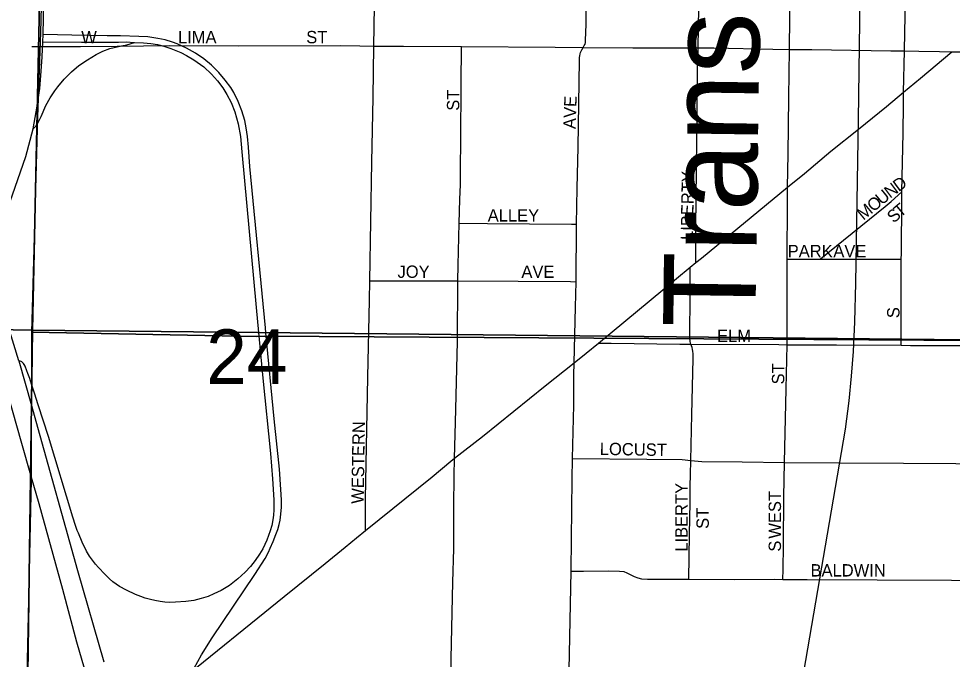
# Model space of a CAD drawing. Extents: x 0 to 68, y 0 to 52.9.
# Drawn here: x 43.122 to 43.878, y 37.686 to 38.205 of the extents above; entities that cross this region are included whole.
import ezdxf

# ---------------------------------------------------------------- set-up
doc = ezdxf.new("R2010")
doc.units = 0
for name, color, linetype in [('Default', 7, 'Continuous'), ('GM_X_County_Road', 7, 'Continuous'), ('GM_X_State_Route', 7, 'Continuous'), ('GM_X_Township', 7, 'Continuous')]:
    doc.layers.add(name, color=color, linetype=linetype)

msp = doc.modelspace()

# ---------------------------------------------------------------- linework, layer by layer
at = {"layer": 'Default'}
for points in [[(41.82896, 39.29088), (43.1609, 39.26536), (43.13273, 37.95279), (41.80876, 37.97561)], [(43.1609, 39.26536), (44.47349, 39.25009), (44.45233, 37.93902), (44.41032, 37.93957), (43.13273, 37.95279)], [(41.80876, 37.97561), (43.13273, 37.95279), (43.11555, 36.67874), (43.11455, 36.64024), (41.78766, 36.70713)], [(43.13273, 37.95279), (44.41032, 37.93957), (44.34414, 36.66665), (43.11555, 36.67874)]]:
    msp.add_lwpolyline(points, close=True, dxfattribs=at)
for points in [[(43.64162, 32.7683), (43.64334, 34.0176), (43.64455, 34.6783), (43.65599, 35.34849), (43.66788, 36.0083), (43.67702, 36.44587), (43.68602, 36.84543), (43.69035, 37.04683), (43.69592, 37.28989), (43.69757, 37.31546), (43.70235, 37.35703), (43.70606, 37.38349), (43.71865, 37.45038), (43.791, 37.87267), (43.79415, 37.89545), (43.79589, 37.91564), (43.79763, 37.93547), (43.7985, 37.95966), (43.79937, 37.99098), (43.80146, 38.12323), (43.80732, 38.54108), (43.80967, 38.71924)], [(43.40919, 38.18305), (43.41081, 38.27968)], [(43.57869, 38.18188), (43.57951, 38.18337), (43.58021, 38.18463), (43.58049, 38.18586), (43.58065, 38.18752), (43.58109, 38.20082), (43.58122, 38.25908), (43.58168, 38.27883)], [(43.67164, 38.18167), (43.67319, 38.26371), (43.67332, 38.27852)], [(43.74576, 38.18028), (43.7465, 38.25844), (43.74697, 38.27753)], [(43.83881, 38.17917), (43.8391, 38.19389), (43.84014, 38.24738), (43.8407, 38.26698), (43.84082, 38.27585)], [(43.26368, 37.67887), (43.26961, 37.68964), (43.27833, 37.70357), (43.31272, 37.75472), (43.32107, 37.76777), (43.32378, 37.77299), (43.32536, 37.77604), (43.32775, 37.78142), (43.32994, 37.78721), (43.33143, 37.7912), (43.33243, 37.79519), (43.33322, 37.79888), (43.33392, 37.80367), (43.33442, 37.80925), (43.33451, 37.81523), (43.33395, 37.8238), (43.33275, 37.84019), (43.32846, 37.88105), (43.32177, 37.95071), (43.32139, 37.95459), (43.3089, 38.08532), (43.30766, 38.10117), (43.30676, 38.10985), (43.30576, 38.11663), (43.30466, 38.12261), (43.30237, 38.13039), (43.29937, 38.13817), (43.29578, 38.14534), (43.29338, 38.14943), (43.28882, 38.15532), (43.28361, 38.16165), (43.2778, 38.16745), (43.27149, 38.1727), (43.26472, 38.17735), (43.25756, 38.18138), (43.25006, 38.1847), (43.24621, 38.18612), (43.24026, 38.18803), (43.23432, 38.18921), (43.22622, 38.19035), (43.219, 38.19082), (43.20413, 38.19128), (43.19338, 38.19141), (43.16465, 38.19183), (43.14133, 38.19231)], [(43.13232, 38.18265), (43.15203, 38.18259), (43.17173, 38.1827), (43.20128, 38.18295), (43.244, 38.18358), (43.29988, 38.18321), (43.38203, 38.18338), (43.39795, 38.18314), (43.40919, 38.18305)], [(43.13345, 38.11605), (43.13577, 38.11838), (43.13752, 38.12094), (43.13973, 38.12583), (43.14372, 38.13492), (43.14698, 38.14092), (43.15081, 38.14661), (43.15326, 38.15006), (43.15857, 38.1563), (43.16435, 38.16211), (43.17021, 38.16716), (43.1773, 38.17194), (43.18428, 38.17613), (43.18964, 38.17881), (43.19545, 38.18091), (43.20481, 38.18306), (43.20907, 38.18406), (43.21536, 38.1858), (43.22257, 38.18557), (43.22865, 38.1851), (43.23398, 38.18419), (43.23922, 38.18279), (43.2448, 38.18105), (43.25283, 38.17767), (43.25748, 38.17534), (43.26355, 38.17186), (43.27146, 38.16604), (43.27764, 38.16023), (43.28271, 38.15471), (43.2869, 38.14912), (43.29008, 38.14364), (43.29362, 38.13735), (43.29658, 38.12968), (43.29933, 38.11985), (43.30132, 38.10959), (43.30227, 38.09717), (43.31391, 37.97108), (43.31584, 37.95077), (43.31934, 37.91399), (43.32541, 37.85284), (43.32714, 37.83238), (43.32833, 37.81532), (43.32824, 37.80715), (43.32804, 37.80296), (43.32744, 37.79917), (43.32645, 37.79449), (43.32525, 37.7902), (43.32395, 37.78651), (43.32246, 37.78272), (43.31917, 37.77564), (43.31659, 37.77125), (43.313, 37.76617), (43.30921, 37.76138), (43.30512, 37.75669), (43.29904, 37.7512), (43.29237, 37.74602), (43.28549, 37.74182), (43.27971, 37.73903), (43.27502, 37.73703), (43.26944, 37.73524), (43.26336, 37.73384), (43.25698, 37.73293), (43.2485, 37.73233), (43.24372, 37.73224), (43.24003, 37.73243), (43.23624, 37.73292), (43.23195, 37.73372), (43.22836, 37.73462), (43.22397, 37.73571), (43.22039, 37.73691), (43.21629, 37.7385), (43.20902, 37.74199), (43.20313, 37.74518), (43.19795, 37.74886), (43.19515, 37.75126), (43.19146, 37.75495), (43.18618, 37.76043), (43.18375, 37.76329), (43.17889, 37.76978), (43.1764, 37.77378), (43.1729, 37.78096), (43.16991, 37.78824), (43.16906, 37.79051)], [(43.1412, 38.18642), (43.17243, 38.1862), (43.19013, 38.18621), (43.2024, 38.18622), (43.20852, 38.18632), (43.21536, 38.1858)], [(43.4059, 37.99287), (43.40762, 38.08886), (43.4085, 38.1414), (43.40919, 38.18305)], [(43.40919, 38.18305), (43.42365, 38.18293), (43.43332, 38.18291), (43.48019, 38.18263)], [(43.47836, 38.03937), (43.47892, 38.05871), (43.47922, 38.07081), (43.47942, 38.0889), (43.47974, 38.10146), (43.47997, 38.15761), (43.48014, 38.17717), (43.48019, 38.18263)], [(43.48019, 38.18263), (43.55598, 38.18218), (43.57869, 38.18188)], [(43.57327, 38.03856), (43.57388, 38.06772), (43.57458, 38.10113), (43.5756, 38.17138), (43.57564, 38.17375), (43.57586, 38.17516), (43.57611, 38.17662), (43.57651, 38.17791), (43.57747, 38.17989), (43.57869, 38.18188)], [(43.57869, 38.18188), (43.61876, 38.18153), (43.67164, 38.18167)], [(43.66992, 38.00751), (43.66987, 38.0153), (43.66976, 38.03616), (43.67003, 38.0589), (43.67086, 38.13228), (43.67125, 38.16453), (43.67164, 38.18167)], [(43.67164, 38.18167), (43.68437, 38.18143), (43.73226, 38.18054), (43.74576, 38.18028)], [(43.74418, 38.06862), (43.74466, 38.09545), (43.74508, 38.14137), (43.74576, 38.18028)], [(43.74576, 38.18028), (43.76385, 38.18031), (43.82786, 38.17919), (43.83881, 38.17917)], [(43.83816, 38.14577), (43.83881, 38.17917)], [(43.83816, 38.14577), (43.85176, 38.15707), (43.87705, 38.17823)], [(43.83881, 38.17917), (43.8504, 38.17888), (43.86711, 38.17847), (43.87705, 38.17823)], [(43.87705, 38.17823), (43.8883, 38.17824), (43.90759, 38.17805), (43.92392, 38.17776), (43.9357, 38.17778)], [(43.74418, 38.06862), (43.75779, 38.0798), (43.77914, 38.09774), (43.80172, 38.1156), (43.82414, 38.13412), (43.83816, 38.14577)], [(43.83676, 38.06499), (43.83773, 38.11282), (43.83803, 38.13575), (43.83816, 38.14577)], [(43.08074, 37.95506), (43.08193, 37.95883), (43.08894, 37.98099), (43.0937, 37.99597), (43.09737, 38.00719), (43.10068, 38.01674), (43.10369, 38.02602), (43.12752, 38.09359), (43.13345, 38.11605)], [(43.66992, 38.00751), (43.67435, 38.01119), (43.74418, 38.06862)], [(43.74385, 38.01033), (43.74399, 38.05619), (43.74418, 38.06862)], [(43.7706, 38.01039), (43.77669, 38.01532), (43.82325, 38.05294), (43.82793, 38.05711), (43.83676, 38.06499)], [(43.83626, 38.01022), (43.83628, 38.01491), (43.83633, 38.03226), (43.83672, 38.04165), (43.83676, 38.06499)], [(43.47724, 37.99278), (43.47735, 38.00555), (43.47836, 38.03937)], [(43.47836, 38.03937), (43.50121, 38.03911), (43.5692, 38.03879), (43.57327, 38.03856)], [(43.57291, 37.99208), (43.57327, 38.03856)], [(43.74378, 37.94103), (43.74386, 37.98401), (43.74385, 38.01033)], [(43.74385, 38.01033), (43.75072, 38.01034), (43.7706, 38.01039)], [(43.7706, 38.01039), (43.78619, 38.01042), (43.8089, 38.01032), (43.82822, 38.01024), (43.83626, 38.01022)], [(43.83619, 37.94051), (43.83624, 37.97093), (43.83622, 38.00225), (43.83626, 38.01022)], [(43.59102, 37.94238), (43.65428, 37.99455), (43.6654, 38.00376)], [(43.66582, 37.94142), (43.66535, 37.94348), (43.66517, 37.94451), (43.66505, 37.94579), (43.66526, 37.98291), (43.66534, 37.99564), (43.6654, 38.00376)], [(43.6654, 38.00376), (43.66992, 38.00751)], [(43.12166, 37.92796), (43.11244, 37.95802), (43.1019, 37.99242), (43.10003, 37.99853)], [(43.40232, 37.79036), (43.40232, 37.79663), (43.40235, 37.8162), (43.40444, 37.91473), (43.40563, 37.97717), (43.4059, 37.99287)], [(43.4059, 37.99287), (43.41018, 37.99287), (43.46268, 37.99289), (43.47724, 37.99278)], [(43.47449, 37.84897), (43.47528, 37.87789), (43.4768, 37.94354), (43.47724, 37.99278)], [(43.47724, 37.99278), (43.52615, 37.9925), (43.56832, 37.99209), (43.57291, 37.99208)], [(43.57132, 37.92636), (43.57241, 37.97144), (43.57291, 37.99208)], [(43.57132, 37.92636), (43.58117, 37.93427), (43.59102, 37.94238)], [(43.59102, 37.94238), (43.60143, 37.94222), (43.6569, 37.94139), (43.66582, 37.94142)], [(43.66577, 37.84721), (43.66661, 37.88438), (43.66759, 37.92953), (43.66765, 37.93191), (43.66768, 37.9337), (43.66743, 37.93583), (43.6672, 37.93717), (43.66684, 37.93864), (43.66633, 37.94007), (43.66582, 37.94142)], [(43.66582, 37.94142), (43.73719, 37.94104), (43.74378, 37.94103)], [(43.74177, 37.84555), (43.74313, 37.90532), (43.74378, 37.94103)], [(43.74378, 37.94103), (43.7837, 37.94093), (43.83619, 37.94051)], [(43.83619, 37.94051), (43.84381, 37.94044), (43.92183, 37.94037), (43.93312, 37.94035)], [(43.16906, 37.79051), (43.16754, 37.79459), (43.16542, 37.8013), (43.1457, 37.86654), (43.13738, 37.89228), (43.13435, 37.90183), (43.13205, 37.90897), (43.13057, 37.91356), (43.12902, 37.91767), (43.12822, 37.91992), (43.12674, 37.92349), (43.12599, 37.92495), (43.12542, 37.92582), (43.12478, 37.92655), (43.12417, 37.9271), (43.12363, 37.92742), (43.1228, 37.92778), (43.12166, 37.92796)], [(43.47449, 37.84897), (43.49725, 37.86675), (43.54797, 37.90769), (43.57132, 37.92636)], [(43.57004, 37.84876), (43.57097, 37.89192), (43.57109, 37.91641), (43.57132, 37.92636)], [(43.40232, 37.79036), (43.45638, 37.834), (43.47144, 37.84662), (43.47449, 37.84897)], [(43.47039, 37.55202), (43.47086, 37.62482), (43.4719, 37.68686), (43.47308, 37.74856), (43.47388, 37.77555), (43.47402, 37.81026), (43.47409, 37.83453), (43.47449, 37.84897)], [(43.56885, 37.7575), (43.56913, 37.78354), (43.56986, 37.8321), (43.57004, 37.84876)], [(43.57004, 37.84876), (43.63009, 37.84827), (43.65869, 37.84788), (43.66577, 37.84721)], [(43.66411, 37.75103), (43.66468, 37.78728), (43.66542, 37.81328), (43.6652, 37.82631), (43.6655, 37.83587), (43.66577, 37.84721)], [(43.66577, 37.84721), (43.67475, 37.84642), (43.7074, 37.84601), (43.74177, 37.84555)], [(43.74046, 37.75084), (43.74061, 37.75882), (43.74097, 37.77822), (43.74114, 37.81776), (43.74177, 37.84555)], [(43.74177, 37.84555), (43.78628, 37.84534), (43.83811, 37.84494), (43.92279, 37.84456), (43.93148, 37.84452)], [(43.38597, 37.77701), (43.39518, 37.78461), (43.40232, 37.79036)], [(43.21006, 37.63545), (43.22377, 37.6466), (43.24225, 37.66065), (43.24996, 37.66663), (43.33669, 37.73692), (43.36987, 37.76372), (43.38597, 37.77701)], [(43.56516, 37.5508), (43.56543, 37.5563), (43.56592, 37.58308), (43.56598, 37.61095), (43.56885, 37.7575)], [(43.56885, 37.7575), (43.57883, 37.75761), (43.5988, 37.75766), (43.60819, 37.75755), (43.61152, 37.75718), (43.61411, 37.75619), (43.61732, 37.75459), (43.62004, 37.75323), (43.62288, 37.75212), (43.62577, 37.75141), (43.6308, 37.75112), (43.64327, 37.75112), (43.65882, 37.75106), (43.66411, 37.75103)], [(43.66411, 37.75103), (43.70123, 37.75076), (43.73334, 37.75089), (43.74046, 37.75084)], [(43.74046, 37.75084), (43.7601, 37.75072), (43.81678, 37.75047), (43.87684, 37.75027), (43.92254, 37.74984), (43.92977, 37.74977)]]:
    msp.add_lwpolyline(points, dxfattribs=at)
at = {"layer": 'GM_X_County_Road'}
for points in [[(43.14133, 38.19231), (43.14239, 38.24528)], [(43.1412, 38.18642), (43.14133, 38.19231)], [(43.13345, 38.11605), (43.13669, 38.13439), (43.13874, 38.14863), (43.13994, 38.16254), (43.14063, 38.17436), (43.1412, 38.18642)]]:
    msp.add_lwpolyline(points, dxfattribs=at)
at = {"layer": 'GM_X_State_Route'}
for points in [[(43.12166, 37.92796), (43.13198, 37.89165), (43.13555, 37.87905), (43.16934, 37.75816), (43.19055, 37.684)], [(43.10601, 37.92348), (43.12327, 37.86315), (43.13171, 37.83367), (43.13783, 37.81229), (43.1571, 37.74301), (43.16849, 37.70023), (43.17463, 37.67898)]]:
    msp.add_lwpolyline(points, dxfattribs=at)
at = {"layer": 'GM_X_Township'}
for points in [[(50.34506, 37.77433), (49.87003, 37.78728), (49.7424, 37.78907), (49.09193, 37.81286), (48.42924, 37.83782), (47.97584, 37.8521), (47.09341, 37.87493), (46.43542, 37.88698), (45.78152, 37.90751), (45.76356, 37.9078), (44.77759, 37.93161), (44.12143, 37.94309), (43.3203, 37.94792), (43.31455, 37.9477), (43.13228, 37.95106), (43.13722, 38.12535), (43.1394, 38.18651), (43.13947, 38.19396), (43.15039, 38.61621), (43.15805, 38.89613)], [(43.06441, 32.7683), (43.08393, 33.99592), (43.08445, 34.02868), (43.09249, 34.65268), (43.09292, 34.68642), (43.10458, 35.31419), (43.1053, 35.34562), (43.1113, 36.01383), (43.1191, 36.64269), (43.12347, 37.01757), (43.12518, 37.25841), (43.12908, 37.42523), (43.12464, 37.49311), (43.12504, 37.51468), (43.13199, 37.8314), (43.13205, 37.85841), (43.13228, 37.95106), (43.31455, 37.9477), (43.3203, 37.94792), (44.12143, 37.94309), (44.77759, 37.93161), (45.76356, 37.9078)]]:
    msp.add_lwpolyline(points, dxfattribs=at)

# ---------------------------------------------------------------- texts
at = {"layer": 'Default'}
for s, height, rotation, p in [('Transportation,', 0.07475, 89.17029, (43.71802, 37.95448)), ('W', 0.01, 0.00001, (43.17226, 38.18526)), ('LIMA', 0.01, 0.00001, (43.25058, 38.18526)), ('ST', 0.01, 0.00001, (43.35442, 38.18526)), ('ST', 0.01, 90, (43.47837, 38.13058)), ('AVE', 0.01, 88.02609, (43.57253, 38.11568)), ('LIBERTY', 0.01, 89.04733, (43.66758, 38.02582)), ('N', 0.01, 36.89175, (43.82713, 38.05925)), ('D', 0.01, 36.37602, (43.83415, 38.06452)), ('U', 0.01, 39.14793, (43.82039, 38.05376)), ('M', 0.01, 39.76359, (43.80553, 38.04139)), ('O', 0.01, 39.79044, (43.81365, 38.04814)), ('T', 0.01, 39.97, (43.83533, 38.04366)), ('ALLEY', 0.01, 0.00001, (43.50138, 38.04082)), ('S', 0.01, 41.48151, (43.83011, 38.03904)), ('PARK', 0.01, 0.00001, (43.74426, 38.0119)), ('AVE', 0.01, 0.00001, (43.78122, 38.0119)), ('JOY', 0.01, 0.00001, (43.42834, 37.99518)), ('AVE', 0.01, 0.00001, (43.52866, 37.99518)), ('S', 0.01, 90, (43.83477, 37.9625)), ('24', 0.0442, 0.00001, (43.27346, 37.90921)), ('ELM', 0.01, 0.00001, (43.68706, 37.94326)), ('ST', 0.01, 90, (43.7415, 37.90882)), ('WESTERN', 0.01, 89.13239, (43.40094, 37.81205)), ('LOCUST', 0.01, 358.93969, (43.59205, 37.85175)), ('LIBERTY', 0.01, 90, (43.66318, 37.7733)), ('WEST', 0.01, 90, (43.73885, 37.78386)), ('ST', 0.01, 90, (43.68038, 37.79178)), ('S', 0.01, 90, (43.73885, 37.7733)), ('BALDWIN', 0.01, 0.00001, (43.76274, 37.75318))]:
    msp.add_text(s, height=height, rotation=rotation, dxfattribs=at).set_placement(p)

doc.saveas('drawing.dxf')
